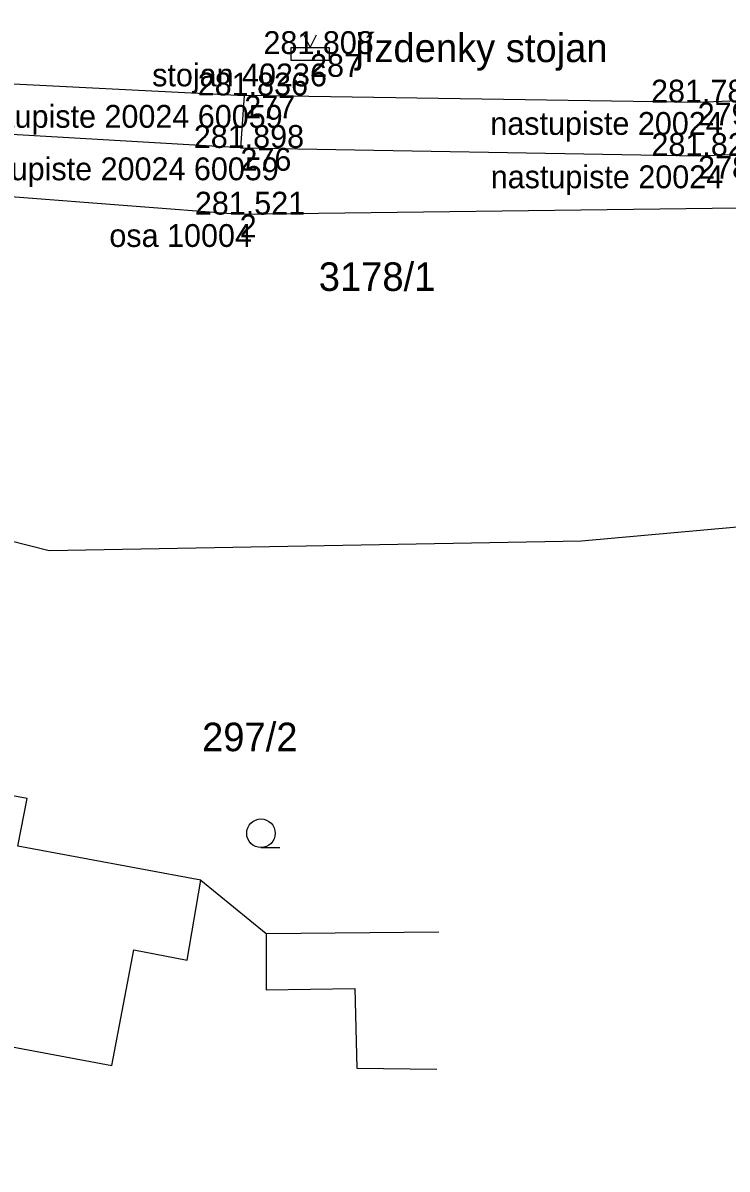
# Model space of a CAD drawing. Extents: x -728659 to -728362, y -1073110 to -1072943.
# Drawn here: x -728492.66 to -728474.14, y -1073069.7 to -1073039.57 of the extents above; entities that cross this region are included whole.
import ezdxf

# ---------------------------------------------------------------- set-up
doc = ezdxf.new("R2010")
doc.units = 0
for name, color, linetype in [('Vrstva 1', 7, 'Continuous'), ('Vrstva 14', 7, 'Continuous'), ('Vrstva 36', 7, 'Continuous'), ('Vrstva 51', 7, 'Continuous'), ('Vrstva 53', 7, 'Continuous'), ('Vrstva 55', 7, 'Continuous'), ('Vrstva 57', 7, 'Continuous'), ('Vrstva 58', 7, 'Continuous'), ('Vrstva 60', 7, 'Continuous'), ('Vrstva 61', 7, 'Continuous'), ('Vrstva 62', 7, 'Continuous')]:
    doc.layers.add(name, color=color, linetype=linetype)

msp = doc.modelspace()

# ---------------------------------------------------------------- linework, layer by layer
at = {"layer": 'Vrstva 1'}
msp.add_lwpolyline([(-728462.112, -1073044.292), (-728486.957, -1073044.611), (-728498.776, -1073043.699), (-728511.695, -1073041.857), (-728514.393, -1073041.361), (-728535.912, -1073035.983), (-728560.369, -1073026.548)], dxfattribs=at)
at = {"layer": 'Vrstva 14'}
msp.add_lwpolyline([(-728461.988, -1073041.13), (-728474.913, -1073041.665), (-728486.835, -1073041.479), (-728486.937, -1073042.858), (-728474.902, -1073043.068), (-728461.886, -1073042.523)], dxfattribs=at)
at = {"layer": 'Vrstva 36'}
msp.add_line((-728485.605, -1073040.227), (-728485.602, -1073040.223), dxfattribs=at)
msp.add_lwpolyline([(-728485.272, -1073039.89), (-728485.105, -1073040.223), (-728484.938, -1073039.89)], dxfattribs=at)
msp.add_lwpolyline([(-728485.605, -1073040.223), (-728484.605, -1073040.223), (-728484.605, -1073040.557), (-728485.605, -1073040.557)], close=True, dxfattribs=at)
at = {"layer": 'Vrstva 51'}
msp.add_lwpolyline([(-728496.482, -1073035.776), (-728497.494, -1073036.644), (-728498.316, -1073037.996), (-728498.528, -1073038.603), (-728498.459, -1073039.486), (-728498.149, -1073040.128), (-728497.533, -1073040.603), (-728496.825, -1073040.892), (-728494.827, -1073041.079), (-728486.835, -1073041.479), (-728486.937, -1073042.858), (-728494.923, -1073042.391), (-728498.977, -1073042.014), (-728499.069, -1073042.727), (-728513.553, -1073040.642)], dxfattribs=at)
at = {"layer": 'Vrstva 53'}
msp.add_lwpolyline([(-728443.68, -1073014.51), (-728493.68, -1073027.94), (-728497.54, -1073030.15), (-728499.78, -1073032.61), (-728501.19, -1073037.94), (-728503.24, -1073052.34), (-728496.81, -1073052.21), (-728491.97, -1073053.44), (-728477.97, -1073053.19), (-728434.587, -1073049.291), (-728361.73, -1073039.5)], dxfattribs=at)
at = {"layer": 'Vrstva 55'}
for points in [[(-728487.98, -1073062.11), (-728492.79, -1073061.21), (-728492.55, -1073059.96), (-728498.42, -1073058.87), (-728498.87, -1073058.79), (-728500.7, -1073068.59)], [(-728494.38, -1073069.7), (-728493.75, -1073066.34), (-728490.32, -1073066.98), (-728489.74, -1073063.94), (-728488.34, -1073064.21), (-728487.98, -1073062.11)], [(-728487.98, -1073062.11), (-728486.26, -1073063.51), (-728481.72, -1073063.46)], [(-728486.26, -1073063.51), (-728486.26, -1073064.99), (-728483.93, -1073064.95), (-728483.88, -1073067.05), (-728481.77, -1073067.07)]]:
    msp.add_lwpolyline(points, dxfattribs=at)
at = {"layer": 'Vrstva 58'}
msp.add_line((-728486.398, -1073061.248), (-728485.898, -1073061.248), dxfattribs=at)
msp.add_circle((-728486.398, -1073060.873), 0.375, dxfattribs=at)
at = {"layer": 'Vrstva 60'}
for p, q in [((-728485.105, -1073040.39), (-728485.105, -1073040.39)), ((-728486.835, -1073041.479), (-728486.835, -1073041.479)), ((-728474.913, -1073041.665), (-728474.913, -1073041.665)), ((-728486.937, -1073042.858), (-728486.937, -1073042.858)), ((-728474.902, -1073043.068), (-728474.902, -1073043.068)), ((-728486.957, -1073044.611), (-728486.957, -1073044.611))]:
    msp.add_line(p, q, dxfattribs=at)

# ---------------------------------------------------------------- texts
at = {"layer": 'Vrstva 36'}
msp.add_text('jízdenky stojan', height=0.75, dxfattribs=at).set_placement((-728483.916, -1073040.603))
at = {"layer": 'Vrstva 57'}
for s, p in [('3178/1', (-728484.878, -1073046.617)), ('297/2', (-728487.946, -1073058.716))]:
    msp.add_text(s, height=0.75, dxfattribs=at).set_placement(p)
at = {"layer": 'Vrstva 60'}
for s, p in [('287', (-728485.105, -1073040.99)), ('277', (-728486.835, -1073042.079)), ('279', (-728474.913, -1073042.265)), ('276', (-728486.937, -1073043.458)), ('278', (-728474.902, -1073043.668)), ('2', (-728486.957, -1073045.211))]:
    msp.add_text(s, height=0.6, dxfattribs=at).set_placement(p)
at = {"layer": 'Vrstva 61'}
for s, p in [('281.808', (-728486.332, -1073040.39)), ('281.836', (-728488.061, -1073041.479)), ('281.783', (-728476.139, -1073041.665)), ('281.898', (-728488.164, -1073042.858)), ('281.829', (-728476.129, -1073043.068)), ('281.521', (-728488.136, -1073044.611))]:
    msp.add_text(s, height=0.6, dxfattribs=at).set_placement(p)
at = {"layer": 'Vrstva 62'}
for s, p in [('stojan 40236', (-728489.259, -1073041.24)), ('nastupiste 20024 60059', (-728494.393, -1073042.329)), ('nastupiste 20024', (-728480.366, -1073042.515)), ('nastupiste 20024 60059', (-728494.495, -1073043.708)), ('nastupiste 20024', (-728480.355, -1073043.918)), ('osa 10004', (-728490.384, -1073045.461))]:
    msp.add_text(s, height=0.6, dxfattribs=at).set_placement(p)

doc.saveas('drawing.dxf')
